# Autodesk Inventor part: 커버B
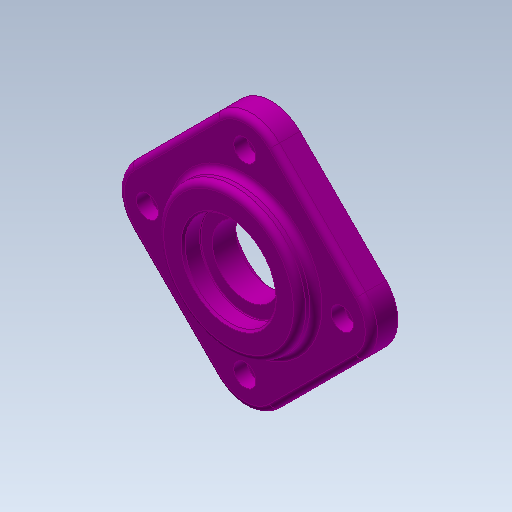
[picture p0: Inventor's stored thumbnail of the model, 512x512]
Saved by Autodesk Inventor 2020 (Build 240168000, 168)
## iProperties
Created: 2013-01
Part Number: 커버B
Document SubType Name: Modeling
Density: 1 g/cm^3
Material: 알루미늄 6061
Designer: mdu
Appearance: 자홍색
Author: mdu
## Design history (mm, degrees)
sketch "스케치1"
  geometry: L1 (56.569, -14.142)-(14.142, -56.569) reference; L2 (-14.142, -56.569)-(-56.569, -14.142) reference; L3 (-56.569, 14.142)-(-14.142, 56.569) reference; L4 (14.142, 56.569)-(56.569, 14.142) reference; C1 r 31 at (0, 0) reference; A1 r 20 centre (0, -42.426) between (-14.142, -56.569) and (14.142, -56.569) reference; A2 r 20 centre (-42.426, 0) between (-56.569, 14.142) and (-56.569, -14.142) reference; A3 r 20 centre (0, 42.426) between (14.142, 56.569) and (-14.142, 56.569) reference; A4 r 20 centre (42.426, 0) between (56.569, -14.142) and (56.569, 14.142) reference; 1 further point
extrude "돌출1" new body sketch "스케치1" distance "d0" = 13; taper "d1" = 0 deg
sketch "스케치2"
  geometry: C1 r 35 at (0, 0); 1 further point
  constraints: 1 centre point, 1 coincident
  dimensions: "d2" = 70 diameter of C1
extrude "돌출2" join sketch "스케치2" distance "d3" = 8; taper "d4" = 0 deg
fillet "모깎기1" dims "d5" = 3
sketch "스케치3"
  geometry: C1 r 2.458 at (0, 48) reference; 1 further point
hole "구멍1" sketch "스케치3" at (0, 48) diameter "d6" = 6.6; stored, may be unused: countersink angle "d10" = 90 deg, drill point angle "d12" = 118 deg; dims "d7" = 6, "d8" = 11, "d9" = 6.5, "d11" = 8
hole "구멍2" diameter "d18" = 33; stored, may be unused: countersink angle "d22" = 90 deg, drill point angle "d24" = 118 deg; dims "d19" = 6, "d20" = 45, "d21" = 8.5, "d23" = 8, "d41" = 10, "d42" = 10
sketch "스케치4"
  geometry: C1 r 31 at (0, 0) reference; 1 further point
extrude "돌출3" join sketch "스케치4" distance "d25" = 6; taper "d26" = 0 deg
hole "구멍3" diameter "d29" = 50; stored, may be unused: countersink angle "d33" = 90 deg, drill point angle "d35" = 0 deg; dims "d27" = 10, "d28" = 10, "d30" = 6, "d31" = 42, "d32" = 8.5, "d34" = 7
fillet "모깎기2" dims "d36" = 3, "d37" = 0.4
chamfer "모따기1" distance "d38" = 1; stored, may be unused: second distance "d39" = 2, angle "d40" = 45 deg
node "솔리드1"
pattern_circular "원형 패턴1" dims angle "d14" = 360 deg
node "참조1"
node "참조2"
node "참조3"
node "참조4"
node "참조5"
node "참조6"
node "참조7"
node "참조8"
node "참조9"
node "참조10"
node "참조11"
